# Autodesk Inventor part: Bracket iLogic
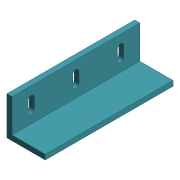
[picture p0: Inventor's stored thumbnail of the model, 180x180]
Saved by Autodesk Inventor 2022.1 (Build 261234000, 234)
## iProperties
Created: 2021-08
Part Number: Bracket iLogic
Material: アルミニウム 6061
Document SubType Name: Modeling
Designer: taeku
Density: 2.7 g/cm^3
Appearance: くすんだ青
Author: taeku
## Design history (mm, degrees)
sketch "スケッチ1"
  geometry: L1 (0, 0)-(30, 0); L2 (30, 0)-(30, 4); L3 (30, 4)-(4, 4); L4 (4, 4)-(4, 30); L5 (4, 30)-(0, 30); L6 (0, 30)-(0, 0)
  constraints: 12 end point, 5 perpendicular, 1 horizontal, 1 vertical
  dimensions: "幅" = 30 distance of L1.start L1.end; "d1" = 30 distance of L5.end L1.start (= 幅); "厚み" = 4 distance of L1.end L2.end
extrude "押し出し1" new body sketch "スケッチ1" taper "d4" = 0 deg
sketch "スケッチ2"
  geometry: L1 (15, 17)-(15, 9); L2 (12.5, 17)-(12.5, 9); L3 (17.5, 9)-(17.5, 17); L4 (0, 0)-(0, 26) reference; A1 r 2.5 centre (15, 17) between (17.5, 17) and (12.5, 17); A2 r 2.5 centre (15, 9) between (12.5, 9) and (17.5, 9); 3 further points
  constraints: 8 end point, 4 point on circle, 4 tangent, 2 centre point, 2 midpoint, 1 horizontal alignment, 1 parallel, 1 vertical
  dimensions: "端からの距離" = 15 distance between parallel lines of L1 L4; "d6" = 8 distance of L1.start L1.end; "d7" = 5 distance between parallel lines of L3 L2
extrude "押し出し2" cut sketch "スケッチ2" extent not by distance; stored distance "d8" = 0; taper "d9" = 0 deg
pattern_linear "矩形状パターン1" dims "d12" = 35 (derived)
node "作業平面1"
sketch "スケッチ3"
  geometry: L1 (26, -9)-(0, -9) reference; L2 (0, 0)-(0, 8) reference; L3 (0, 5.364)-(14.364, -9); 1 further point
  constraints: 2 end point, 2 point on line
  dimensions: "d13" = 45 deg angle of L3 L1
feature "リブ1" sketch "スケッチ3" dims "d14" = 1, "d15" = 3, "d16" = 0, "d17" = 0, "d18" = 1, "d19" = 1
node "作業平面2"
mirror "ミラー1"
node "ソリッド1"
